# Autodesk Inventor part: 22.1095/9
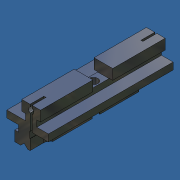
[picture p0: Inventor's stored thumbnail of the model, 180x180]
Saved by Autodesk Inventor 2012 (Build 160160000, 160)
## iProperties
Created: 2007-06
Part Number: 22.1095/9
Material: UHMW, Black
Document SubType Name: Modeling
Designer: Andy Moles
Density: 0.94 g/cm^3
Description: MACHINE TO 22.1095/9
Mass: 32.5039 g
Surface Area: 140.586 cm^2
Volume: 34.5786 cm^3
Stock Number: 22.1095/1
Author: Andy Moles
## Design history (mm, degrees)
sketch "Sketch1"
  geometry: L1 (4.1, 0)-(4.1, -4.6) reference; L2 (17.5, 0)-(4.1, 0) reference; L3 (17.5, 5)-(17.5, 0) reference; L4 (9.1, 5)-(17.5, 5) reference; L5 (9.1, 9.6)-(9.1, 5) reference; L6 (11.75, 9.6)-(9.1, 9.6) reference; L7 (11.75, 17)-(11.75, 9.6) reference; L8 (-1.75, 17)-(11.75, 17) reference; L9 (-1.75, 9.6)-(-1.75, 17) reference; L10 (0.9, 9.6)-(-1.75, 9.6) reference; L11 (0.9, 5)-(0.9, 9.6) reference; L12 (-12.5, 5)-(0.9, 5) reference; L13 (-12.5, 0)-(-12.5, 5) reference; L14 (-4.1, 0)-(-12.5, 0) reference; L15 (-4.1, -4.6)-(-4.1, 0) reference; L16 (-6.75, -4.6)-(-4.1, -4.6) reference; L17 (-6.75, -12)-(-6.75, -4.6) reference; L18 (6.75, -4.6)-(6.75, -12) reference; L19 (4.1, -4.6)-(6.75, -4.6) reference; L20 (-2.5, -12)-(0, -9.5); L21 (0, -9.5)-(2.5, -12); L22 (6.75, -12)-(2.5, -12); L23 (-2.5, -12)-(-6.75, -12); 4 further points
  constraints: 46 end point, 11 horizontal, 10 vertical, 1 midpoint, 1 perpendicular, 1 vertical alignment, 21 other
  dimensions: "d1" = 90 deg angle of L21 L20
extrude "Extrusion1" new body sketch "Sketch1" stored distance "d2" = 90; taper "d3" = 0 deg
sketch "Sketch2"
  geometry: L1 (4.25, 0)-(0, 0) reference; L2 (4.25, -90)-(4.25, 0) reference; L3 (1.75, -9.67)-(1.75, 0); L4 (-9.25, -90)-(-9.25, 0) reference; A1 r 5 centre (6.75, -9.67) between (1.75, -9.67) and (4.25, -14); 1 further point
  constraints: 2 end point, 2 point on circle, 2 point on line, 1 centre point, 1 parallel, 1 tangent
  dimensions: "d4" = 10 diameter of A1; "d5" = 11 distance between parallel lines of L3 L4; "d6" = 14 distance from line of A1.end L1
extrude "Extrusion2" cut sketch "Sketch2" distance "d7" = 12; taper "d8" = 0 deg
sketch "Sketch3"
  geometry: L1 (-1.75, 17)-(11.75, 17) reference; L2 (-1.75, 9.6)-(-1.75, 17) reference; L3 (4.25, -12)-(2.5, -12) reference; L4 (4.25, -3.157)-(5.75, -3.157); L5 (4.25, 17)-(4.25, 15.154); L6 (4.25, 11.446)-(4.25, -3.157); L7 (5.75, -3.157)-(5.75, 11.446); L8 (5.75, 15.154)-(5.75, 17); L9 (4.25, 17)-(5.75, 17); A1 r 2 centre (5, 13.3) between (4.25, 15.154) and (4.25, 11.446); A2 r 2 centre (5, 13.3) between (5.75, 11.446) and (5.75, 15.154); 6 further points
  constraints: 12 end point, 5 midpoint, 4 parallel, 4 perpendicular, 4 point on circle, 3 vertical alignment, 2 centre point, 2 point on line, 1 collinear, 1 horizontal alignment
  dimensions: "d9" = 1.5 distance of L4.start L4.end
extrude "Extrusion3" cut sketch "Sketch3" distance "d11" = 10; taper "d12" = 0 deg
mirror "Mirror1"
thread "Thread1" dims "d13" = 10, "d14" = 0
thread "Thread2" dims "d15" = 10, "d16" = 0
thread "Thread3" dims "d17" = 10, "d18" = 0
thread "Thread4" dims "d19" = 10, "d20" = 0
sketch "Sketch4"
  geometry: L1 (0, 90)-(0, 0) reference; L2 (13.5, 90)-(13.5, 0) reference; L3 (0, 37.863)-(13.5, 37.863); L4 (13.5, 37.863)-(13.5, 52.137); L5 (13.5, 52.137)-(0, 52.137); L6 (0, 52.137)-(0, 37.863); 2 further points
  constraints: 8 end point, 2 parallel, 2 point on line, 1 horizontal, 1 horizontal alignment, 1 midpoint, 1 perpendicular
  dimensions: "d21" = 14.2748 distance between parallel lines of L3 L5
extrude "Extrusion4" cut sketch "Sketch4" distance "d22" = 7.62; taper "d23" = 0 deg
sketch "Sketch5"
  geometry: L1 (10.85, 52.137)-(2.65, 52.137) reference; L2 (2.65, 37.863)-(2.65, 52.137) reference; L3 (2.65, 37.863)-(10.85, 37.863) reference; L4 (10.85, 52.137)-(10.85, 37.863) reference; L5 (0, 52.137)-(13.5, 52.137) reference; C1 r 3.25 at (6.75, 45); 2 further points
  constraints: 1 centre point, 1 horizontal alignment, 1 midpoint, 1 vertical alignment
  dimensions: "d26" = 6.5 diameter of C1
extrude "Extrusion5" cut sketch "Sketch5" stored distance "d24" = 7.62; taper "d25" = 0 deg
body "Solid1"
node "Projected Loop1"
other parameters: "d0" = 2.5, "d10" = 4
